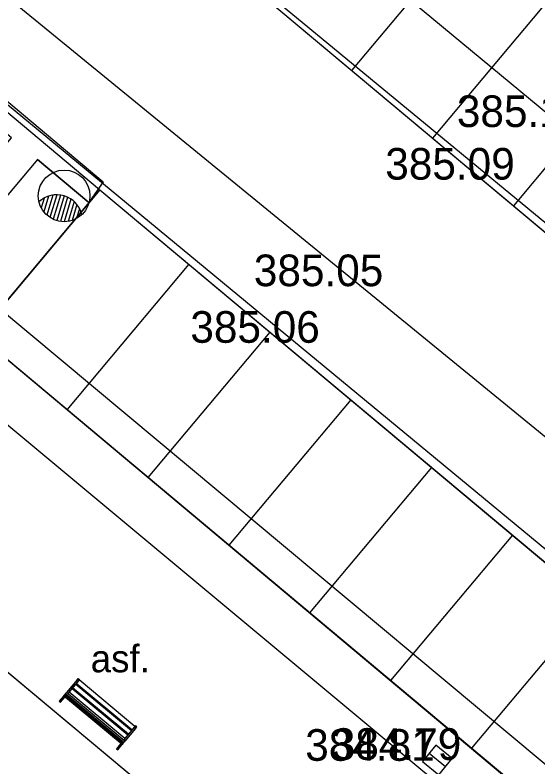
# Model space of a CAD drawing. Extents: x -438233 to -437334, y -1133133 to -1132623.
# Drawn here: x -438100.33 to -438087.94, y -1132995.04 to -1132977.21 of the extents above; entities that cross this region are included whole.
import ezdxf

# ---------------------------------------------------------------- set-up
doc = ezdxf.new("R2010")
doc.units = 0
for name, color, linetype in [('EL3', 7, 'Continuous'), ('MOBILIÁŘ', 7, 'Continuous'), ('Vrstva 1', 7, 'Continuous'), ('Vrstva 10', 7, 'Continuous'), ('Vrstva 15', 7, 'Continuous'), ('Vrstva 27', 7, 'Continuous'), ('Vrstva 3', 7, 'Continuous'), ('Vrstva 40', 7, 'Continuous'), ('Vrstva 5', 7, 'Continuous'), ('Vrstva 50', 7, 'Continuous'), ('Vrstva 53', 7, 'Continuous'), ('Vrstva 55', 7, 'Continuous')]:
    doc.layers.add(name, color=color, linetype=linetype)

# ---------------------------------------------------------------- blocks, each defined once
blk = doc.blocks.new('A$C6FF56919')
at = {"layer": 'Vrstva 1'}
for p, q in [((-18000, 5423), (-18000, 5482)), ((-18000, 5482), (-17605, 5482)), ((-18000, 5423), (0, 5423)), ((-18000, 5108), (-18000, 5423)), ((-17605, 5482), (-17605, 7031)), ((-17605, 5423), (-17605, 5482)), ((-401, 7031), (-401, 5482)), ((0, 7031), (-401, 7031)), ((-401, 5482), (0, 5482)), ((-401, 5423), (-401, 5482)), ((0, 5482), (0, 7031)), ((0, 5423), (0, 5482)), ((0, 5423), (0, 5108)), ((-18000, 5108), (0, 5108)), ((-18000, 4771), (-18000, 5108)), ((-18000, 4771), (0, 4771)), ((-18000, 4707), (-18000, 4771)), ((0, 4707), (-18000, 4707)), ((-18000, 4707), (-18000, 4365)), ((-18000, 459), (-18000, 4365)), ((-18000, 4365), (0, 4365)), ((-17605, 459), (-17605, 4365)), ((-17605, 3703), (-17594, 3703)), ((-17594, 2805), (-17594, 3895)), ((-401, 3703), (-411, 3703)), ((-401, 459), (-401, 4365)), ((0, 5108), (0, 4771)), ((0, 4771), (0, 4707)), ((0, 4365), (0, 4707)), ((0, 459), (0, 4365)), ((-17605, 2907), (-17594, 2907)), ((-17605, 2901), (-17594, 2901)), ((-17605, 2410), (-17594, 2410)), ((-411, 2805), (-17594, 2805)), ((-17594, 2805), (-17594, 2762)), ((-17594, 2762), (-411, 2762)), ((-17594, 2575), (-411, 2575)), ((-17594, 1475), (-17594, 2575)), ((-9200, 2575), (-9200, 2762)), ((-8799, 2575), (-8799, 2762)), ((-401, 2907), (-411, 2907)), ((-401, 2901), (-411, 2901)), ((-411, 2762), (-411, 2805)), ((-411, 2575), (-411, 1475)), ((-401, 2410), (-411, 2410)), ((-18000, 459), (-18000, 0)), ((-17605, 459), (-18000, 459)), ((-18000, 0), (-17605, 0)), ((-17605, 1608), (-17594, 1608)), ((-17605, 1608), (-17594, 1608)), ((-17605, 1106), (-17594, 1106)), ((-17605, 1106), (-17594, 1106)), ((-17605, 0), (-17605, 459)), ((-17605, 305), (-17594, 305)), ((-17594, 1459), (-17594, 1475)), ((-17594, 1475), (-411, 1475)), ((-411, 1459), (-17594, 1459)), ((-17594, 1245), (-17594, 1256)), ((-17594, 1256), (-411, 1256)), ((-17594, 1245), (-17594, 144)), ((-411, 1245), (-17594, 1245)), ((-17594, 144), (-411, 144)), ((-9200, 1256), (-9200, 1459)), ((-8800, 1256), (-8800, 1459)), ((-401, 1608), (-411, 1608)), ((-401, 1608), (-411, 1608)), ((-411, 1475), (-411, 1459)), ((-411, 1256), (-411, 1245)), ((-411, 144), (-411, 1245)), ((-401, 1106), (-411, 1106)), ((-401, 1106), (-411, 1106)), ((-401, 305), (-411, 305)), ((-401, 459), (0, 459)), ((-401, 0), (-401, 459)), ((0, 0), (-401, 0)), ((0, 459), (0, 0))]:
    blk.add_line(p, q, dxfattribs=at)
for points in [[(-17605, 7031), (-18000, 7031), (-18000, 5482)], [(-17594, 3895), (-411, 3895), (-411, 2805)]]:
    blk.add_lwpolyline(points, dxfattribs=at)
blk = doc.blocks.new('ELJL31_2_1')
at = {"layer": 'EL3'}
for p, q in [((10.50516, 25), (24.4949, 25)), ((3.37727, 15), (31.62278, 15)), ((6.27724, 20), (28.72281, 20)), ((0, 0), (35, 0)), ((0.35902, 5), (34.64102, 5)), ((1.45902, 10), (33.54102, 10)), ((0.35902, -5), (34.64102, -5)), ((1.45902, -10), (33.54102, -10)), ((3.37727, -15), (31.62278, -15)), ((6.27724, -20), (28.72281, -20)), ((10.50516, -25), (24.4949, -25))]:
    blk.add_line(p, q, dxfattribs=at)
blk.add_circle((0, 0), 35, dxfattribs=at)
blk.add_arc((35, 0), 34.99996, 119.999947, 239.999954, dxfattribs=at)

msp = doc.modelspace()

# ---------------------------------------------------------------- linework, layer by layer
at = {"layer": 'Vrstva 1'}
for p, q in [((-438115.61, -1132966.865), (-438098.33, -1132981.342)), ((-438089.469, -1132975.068), (-438092.359, -1132978.517)), ((-438089.469, -1132975.068), (-438092.359, -1132978.517)), ((-438094.467, -1132976.751), (-438069.171, -1132997.943)), ((-438087.552, -1132976.673), (-438090.442, -1132980.123)), ((-438085.636, -1132978.279), (-438088.526, -1132981.728)), ((-438089.06, -1132981.108), (-438089.06, -1132981.108)), ((-438098.32, -1132981.35), (-438101.21, -1132984.8)), ((-438098.32, -1132981.35), (-438073.024, -1133002.543)), ((-438096.212, -1132983.116), (-438099.102, -1132986.566)), ((-438092.174, -1132983.635), (-438092.174, -1132983.635)), ((-438101.21, -1132984.8), (-438075.914, -1133005.992)), ((-438094.295, -1132984.722), (-438097.185, -1132988.171)), ((-438093.679, -1132984.977), (-438093.679, -1132984.977)), ((-438092.379, -1132986.327), (-438095.269, -1132989.777)), ((-438090.463, -1132987.933), (-438093.352, -1132991.382)), ((-438088.546, -1132989.538), (-438091.436, -1132992.988)), ((-438086.63, -1132991.144), (-438089.52, -1132994.593)), ((-438090.957, -1132994.89), (-438090.957, -1132994.89)), ((-438090.328, -1132994.868), (-438090.328, -1132994.868))]:
    msp.add_line(p, q, dxfattribs=at)
at = {"layer": 'Vrstva 10'}
msp.add_lwpolyline([(-438136.916, -1132976.04), (-438130.815, -1132968.777), (-438110.909, -1132985.383), (-438109.206, -1132983.342), (-438101.698, -1132989.616), (-438102.771, -1132990.9), (-438091.189, -1133000.578), (-438097.908, -1133008.583)], close=True, dxfattribs=at)
for points in [[(-438095.722, -1132972.904), (-438079.649, -1132986.224)], [(-438097.077, -1132974.44), (-438080.864, -1132987.825)], [(-438100.332, -1132976.931), (-438084.087, -1132990.217)], [(-438101.653, -1132978.388), (-438085.456, -1132991.774)], [(-438106.458, -1132981.967), (-438090.957, -1132994.89), (-438086.882, -1132998.283), (-438085.153, -1132999.203), (-438079.851, -1133001.541), (-438076.272, -1133002.948)]]:
    msp.add_lwpolyline(points, dxfattribs=at)
at = {"layer": 'Vrstva 15'}
for q in [(-438105.012, -1132986.847), (-438098.587, -1132981.649)]:
    msp.add_line((-438099.803, -1132980.63), q, dxfattribs=at)
msp.add_lwpolyline([(-438101.643, -1132979.088), (-438101.288, -1132978.609), (-438098.247, -1132981.16), (-438098.587, -1132981.649), (-438099.803, -1132980.63), (-438105.012, -1132986.847), (-438105.626, -1132986.334), (-438100.416, -1132980.116)], close=True, dxfattribs=at)
at = {"layer": 'Vrstva 27'}
msp.add_line((-438090.522, -1132994.71), (-438090.134, -1132995.026), dxfattribs=at)
msp.add_lwpolyline([(-438090.68, -1132994.903), (-438090.293, -1132995.22), (-438089.976, -1132994.833), (-438090.363, -1132994.516)], close=True, dxfattribs=at)
at = {"layer": 'Vrstva 5'}
msp.add_line((-438091.189, -1133000.578), (-438102.771, -1132990.9), dxfattribs=at)
at = {"layer": 'Vrstva 50'}
for points in [[(-438091.577, -1132973.302), (-438066.273, -1132994.5), (-438069.163, -1132997.95), (-438094.467, -1132976.751)], [(-438098.32, -1132981.35), (-438073.025, -1133002.541), (-438075.915, -1133005.991), (-438101.21, -1132984.8)]]:
    msp.add_lwpolyline(points, close=True, dxfattribs=at)
at = {"layer": 'Vrstva 55'}
msp.add_lwpolyline([(-438074.959, -1133013.61), (-438076.856, -1133009.846), (-438083.298, -1132998.719), (-438115.192, -1132972.054), (-438146.469, -1132953.711), (-438176.9, -1132931.48)], dxfattribs=at)

# ---------------------------------------------------------------- block references
at = {"layer": 'MOBILIÁŘ', "xscale": 0.0001, "yscale": 0.00010000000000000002, "rotation": 140.22668670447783}
msp.add_blockref('A$C6FF56919', (-438098.834, -1132992.936), dxfattribs=at)
at = {"layer": 'Vrstva 53', "xscale": 0.0175, "yscale": 0.0175, "rotation": -106.66592339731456}
msp.add_blockref('ELJL31_2_1', (-438099.169, -1132981.494), dxfattribs=at)

# ---------------------------------------------------------------- texts
at = {"layer": 'Vrstva 3'}
for s, p in [('385.10 ', (-438089.864, -1132979.861)), ('385.09 ', (-438091.56, -1132981.108)), ('385.05 ', (-438094.674, -1132983.635)), ('385.06 ', (-438096.179, -1132984.977)), ('384.81 ', (-438093.457, -1132994.89)), ('384.79 ', (-438092.828, -1132994.868))]:
    msp.add_text(s, height=0.75, dxfattribs=at).set_placement(p)
at = {"layer": 'Vrstva 40'}
msp.add_text('asf.', height=0.65, dxfattribs=at).set_placement((-438098.539, -1132992.791))

doc.saveas('drawing.dxf')
